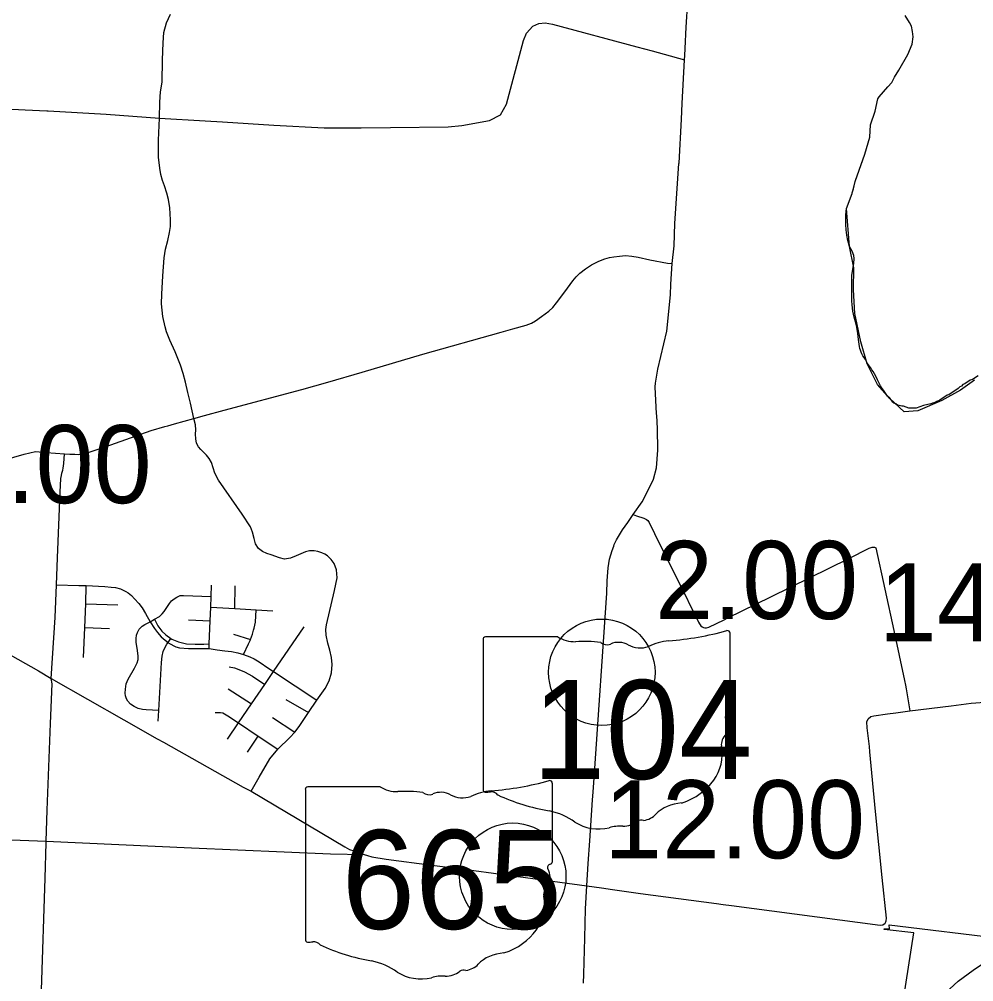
# Model space of a CAD drawing. Extents: x 1659811 to 1934326, y 644115 to 934867.
# Drawn here: x 1810912 to 1824362, y 663921 to 677476 of the extents above; entities that cross this region are included whole.
import ezdxf

# ---------------------------------------------------------------- set-up
doc = ezdxf.new("R2010")
doc.units = 0
for name, color, linetype in [('Default', 7, 'Continuous'), ('GM_X_City_Street', 7, 'Continuous'), ('GM_X_Corporation', 7, 'Continuous'), ('GM_X_County_Road', 7, 'Continuous'), ('GM_X_State_Route', 7, 'Continuous'), ('GM_X_State_Shield', 7, 'Continuous'), ('GM_X_Township', 7, 'Continuous'), ('GM_X_Township_Road', 7, 'Continuous')]:
    doc.layers.add(name, color=color, linetype=linetype)

msp = doc.modelspace()

# ---------------------------------------------------------------- linework, layer by layer
at = {"layer": 'Default'}
for centre in [(1819121, 668279), (1817866, 665407)]:
    msp.add_circle(centre, 750, dxfattribs=at)
at = {"layer": 'GM_X_City_Street'}
for points in [[(1813371, 671853), (1813325, 672068), (1813288, 672219), (1813255, 672367), (1813224, 672487), (1813186, 672606), (1813109, 672790), (1813036, 672955), (1812989, 673072), (1812967, 673143), (1812934, 673292), (1812918, 673466), (1812919, 673605), (1812936, 673864), (1812955, 674114), (1812972, 674238), (1813004, 674362), (1813030, 674473), (1813041, 674557), (1813043, 674649), (1813032, 674821), (1813016, 674937), (1812991, 675029), (1812959, 675131), (1812930, 675207), (1812908, 675291), (1812891, 675379), (1812874, 675536), (1812874, 675771), (1812889, 676084), (1812895, 676306), (1812902, 676452), (1812924, 676588), (1812932, 676903), (1812940, 677144), (1812948, 677290), (1812987, 677426), (1813041, 677549)], [(1819830, 677029), (1820001, 676982), (1820288, 676905)], [(1810161, 676241), (1810328, 676234), (1810996, 676200), (1811302, 676188), (1811320, 676187)], [(1811320, 676187), (1812139, 676140), (1812889, 676084), (1813531, 676044)], [(1812964, 671740), (1813007, 671752), (1813102, 671780), (1813371, 671853)], [(1813371, 671853), (1813524, 671895)], [(1814180, 666603), (1814291, 666801), (1814442, 667062), (1814554, 667195), (1814727, 667360), (1814796, 667438), (1814856, 667514), (1814989, 667712), (1815107, 667885), (1815223, 668049), (1815281, 668158), (1815311, 668272), (1815321, 668387), (1815311, 668487), (1815289, 668592), (1815259, 668688), (1815237, 668800), (1815234, 668881), (1815241, 668947), (1815354, 669430), (1815390, 669609), (1815383, 669721), (1815349, 669811), (1815305, 669869), (1815256, 669921), (1815219, 669941), (1815178, 669963), (1815121, 669980), (1815066, 669988), (1815004, 669988), (1814945, 669974), (1814816, 669918), (1814732, 669884), (1814651, 669874), (1814577, 669890), (1814463, 669931), (1814403, 669953), (1814338, 669980), (1814285, 670023), (1814242, 670088), (1814220, 670164), (1814197, 670252), (1814172, 670328), (1814054, 670505), (1813719, 670987), (1813666, 671083), (1813620, 671234), (1813586, 671292), (1813549, 671336), (1813470, 671416), (1813437, 671455), (1813409, 671506), (1813398, 671565), (1813394, 671634), (1813398, 671695), (1813394, 671765), (1813371, 671853)], [(1810689, 671267), (1810983, 671351), (1811142, 671387), (1811295, 671373), (1811548, 671356)], [(1811438, 669509), (1811752, 669502)], [(1811752, 669502), (1811856, 669500), (1812119, 669485), (1812205, 669479), (1812270, 669471), (1812338, 669454), (1812414, 669418), (1812445, 669399), (1812492, 669359), (1812538, 669315), (1812595, 669248), (1812644, 669186), (1812693, 669108), (1812757, 668992), (1812820, 668894), (1812861, 668838), (1812911, 668777), (1812969, 668731), (1813010, 668700), (1813021, 668691), (1813117, 668638), (1813169, 668624), (1813298, 668612), (1813586, 668612), (1813700, 668595), (1813807, 668582), (1813905, 668570), (1813994, 668554), (1814072, 668528), (1814161, 668495), (1814222, 668470), (1814293, 668425), (1814427, 668331), (1814493, 668288), (1815107, 667885)], [(1811816, 668488), (1811834, 668910), (1811848, 669242), (1811856, 669500)], [(1813586, 668612), (1813589, 668680), (1813602, 669006), (1813610, 669198), (1813616, 669346), (1813623, 669508)], [(1813949, 669178), (1813954, 669498)], [(1812757, 668992), (1812816, 669026), (1812887, 669067), (1812927, 669104), (1812956, 669136), (1813031, 669249), (1813059, 669284), (1813094, 669315), (1813133, 669339), (1813180, 669361), (1813226, 669361), (1813616, 669346)], [(1811848, 669242), (1812300, 669229)], [(1813610, 669198), (1813949, 669178), (1814252, 669159), (1814484, 669145)], [(1814072, 668528), (1814142, 668682), (1814165, 668727), (1814171, 668743), (1814197, 668816), (1814212, 668872), (1814221, 668901), (1814239, 668985), (1814252, 669159)], [(1812877, 667743), (1812699, 667748), (1812649, 667754), (1812586, 667771), (1812533, 667796), (1812482, 667830), (1812444, 667872), (1812423, 667905), (1812409, 667947), (1812405, 667985), (1812407, 668042), (1812420, 668117), (1812449, 668184), (1812536, 668335), (1812575, 668413), (1812589, 668459), (1812587, 668511), (1812572, 668620), (1812559, 668698), (1812558, 668757), (1812564, 668800), (1812579, 668840), (1812603, 668885), (1812643, 668927), (1812680, 668954), (1812757, 668992)], [(1812816, 669026), (1812866, 668932), (1812922, 668857), (1812978, 668807), (1813049, 668755), (1813064, 668745), (1813154, 668709), (1813269, 668682), (1813389, 668673), (1813511, 668677), (1813589, 668680)], [(1813298, 669019), (1813602, 669006)], [(1811834, 668910), (1812186, 668895)], [(1813931, 668818), (1814171, 668743)], [(1814493, 668288), (1814928, 668921)], [(1812868, 667589), (1812877, 667743), (1812917, 668416), (1812927, 668506), (1812942, 668574), (1812967, 668631), (1812993, 668676), (1813010, 668700), (1813049, 668755)], [(1813846, 667336), (1814002, 667566), (1814186, 667836), (1814371, 668107), (1814493, 668288)], [(1813871, 668355), (1813943, 668342), (1814004, 668319), (1814086, 668284), (1814200, 668225), (1814371, 668107)], [(1813858, 668045), (1814186, 667836)], [(1823399, 668099), (1823408, 668048), (1823461, 667737)], [(1814668, 667896), (1814989, 667712)], [(1813672, 667714), (1813716, 667712), (1813746, 667711), (1813781, 667706), (1813852, 667667), (1814002, 667566), (1814278, 667381), (1814554, 667195)], [(1814481, 667641), (1814796, 667438)], [(1814126, 667154), (1814278, 667381)]]:
    msp.add_lwpolyline(points, dxfattribs=at)
at = {"layer": 'GM_X_Corporation'}
for points in [[(1824422, 672453), (1824345, 672402), (1824311, 672393), (1824234, 672342), (1824209, 672333), (1824191, 672308), (1824166, 672299), (1824140, 672274), (1824012, 672188), (1823987, 672180), (1823884, 672112), (1823842, 672095), (1823816, 672078), (1823782, 672069), (1823757, 672060), (1823654, 672035), (1823552, 672001), (1823449, 672001), (1823373, 672026), (1823347, 672026), (1823313, 672035), (1823287, 672043), (1823262, 672060), (1823236, 672069), (1823212, 672089), (1823197, 672115), (1823177, 672141), (1823148, 672170), (1823107, 672222), (1823090, 672252), (1823070, 672278), (1823046, 672313), (1823032, 672342), (1823020, 672368), (1823006, 672400), (1822991, 672429), (1822962, 672481), (1822945, 672513), (1822927, 672539), (1822907, 672571), (1822866, 672629), (1822852, 672658), (1822837, 672685), (1822817, 672711), (1822799, 672737), (1822785, 672763), (1822773, 672789), (1822767, 672815), (1822756, 672841), (1822751, 672869), (1822743, 672935), (1822734, 673004), (1822726, 673056), (1822719, 673105), (1822708, 673162), (1822694, 673214), (1822676, 673282), (1822660, 673367), (1822650, 673455), (1822646, 673511), (1822644, 673569), (1822643, 673637), (1822645, 673698), (1822645, 673747), (1822645, 673805), (1822646, 673867), (1822651, 673929), (1822661, 673984), (1822671, 674038), (1822675, 674106), (1822671, 674150), (1822649, 674212), (1822613, 674277), (1822586, 674362), (1822574, 674436), (1822566, 674509), (1822560, 674586), (1822558, 674651), (1822561, 674723), (1822569, 674813), (1822647, 675022), (1822650, 675033), (1822665, 675087), (1822691, 675193), (1822694, 675207), (1822828, 675577), (1822851, 675655), (1822897, 675813), (1822908, 675991), (1822974, 676180), (1823012, 676355), (1823028, 676384), (1823152, 676525), (1823208, 676586), (1823247, 676661), (1823305, 676759), (1823431, 676978), (1823492, 677123), (1823510, 677230), (1823498, 677303), (1823485, 677377), (1823457, 677430), (1823394, 677531)], [(1823332, 663432), (1823518, 664608), (1823100, 664659), (1823103, 664672), (1823175, 664665), (1823170, 664722), (1824798, 664523)]]:
    msp.add_lwpolyline(points, dxfattribs=at)
at = {"layer": 'GM_X_County_Road'}
msp.add_lwpolyline([(1813531, 676044), (1813778, 676029), (1814498, 675982), (1815209, 675949), (1815732, 675949), (1816142, 675951), (1816958, 675960), (1817150, 675979), (1817539, 676052), (1817692, 676132), (1817778, 676281), (1818016, 677175), (1818058, 677282), (1818149, 677378), (1818232, 677416), (1818323, 677425), (1818424, 677407), (1819616, 677087), (1819830, 677029)], dxfattribs=at)
at = {"layer": 'GM_X_State_Route'}
for points in [[(1820296, 677064), (1820311, 677364), (1820331, 677730), (1820345, 677961), (1820346, 677975), (1820365, 678298), (1820393, 678749), (1820402, 679022)], [(1820288, 676905), (1820291, 676966), (1820296, 677064)], [(1820208, 675444), (1820209, 675449), (1820243, 676069), (1820255, 676288), (1820288, 676905)], [(1819894, 671894), (1819893, 671920), (1819872, 672301), (1819877, 672349), (1819912, 672547), (1820038, 673084), (1820088, 673593), (1820092, 673746), (1820110, 674036), (1820141, 674286), (1820149, 674599), (1820208, 675444)], [(1819288, 670053), (1819297, 670077), (1819327, 670145), (1819411, 670285), (1819487, 670390), (1819563, 670503), (1819691, 670679), (1819757, 670808), (1819851, 671000), (1819892, 671158), (1819910, 671407), (1819904, 671713), (1819894, 671894)], [(1808076, 670072), (1808114, 670051), (1808982, 669552), (1810244, 668838), (1810520, 668670), (1811183, 668298), (1811362, 668191), (1812385, 667611), (1812857, 667344)], [(1819017, 666852), (1819017, 666860), (1819192, 669395), (1819197, 669568), (1819211, 669750), (1819230, 669872), (1819266, 669993), (1819288, 670053)], [(1822891, 667232), (1822862, 667499), (1822856, 667582), (1822875, 667625), (1822910, 667656), (1822955, 667668), (1823148, 667696), (1823266, 667709), (1823461, 667737), (1824045, 667809), (1824325, 667846), (1824516, 667859), (1824733, 667846)], [(1812857, 667344), (1812945, 667295)], [(1812945, 667295), (1814068, 666660), (1814180, 666603), (1815498, 665821), (1815564, 665785), (1815626, 665766), (1815698, 665736), (1815770, 665711), (1815820, 665697), (1815821, 665697)], [(1820946, 664994), (1823042, 664717), (1823082, 664723), (1823115, 664746), (1823124, 664764), (1823128, 664780), (1823130, 664816), (1823073, 665389), (1822978, 666317), (1822899, 667159), (1822891, 667232)], [(1818999, 666589), (1818999, 666596), (1819017, 666852)], [(1818991, 666483), (1818999, 666589)], [(1818951, 665904), (1818991, 666483)], [(1818929, 665588), (1818951, 665904)], [(1815821, 665697), (1815880, 665680), (1816082, 665646), (1816726, 665563), (1817285, 665493)], [(1818908, 665272), (1818929, 665588)], [(1817285, 665493), (1817287, 665493), (1817319, 665489), (1818151, 665376), (1818908, 665272)], [(1818882, 664535), (1818893, 664950), (1818908, 665272)], [(1818908, 665272), (1819117, 665243)], [(1819117, 665243), (1819273, 665220)], [(1819273, 665220), (1819666, 665165), (1820737, 665022)], [(1820737, 665022), (1820831, 665009), (1820946, 664994)], [(1818865, 663903), (1818869, 664029), (1818882, 664535)]]:
    msp.add_lwpolyline(points, dxfattribs=at)
at = {"layer": 'GM_X_State_Shield'}
for p, q in [((1820928, 667725), (1820928, 668830)), ((1817447, 668741), (1817447, 666628)), ((1818501, 668778), (1817481, 668778)), ((1820927, 667725), (1820928, 667725)), ((1815997, 666666), (1814978, 666666)), ((1818424, 665613), (1818424, 666718)), ((1814944, 666629), (1814944, 664516)), ((1818424, 665613), (1818424, 665613))]:
    msp.add_line(p, q, dxfattribs=at)
for centre, major_axis, start_param, end_param in [((1819688, 671659), (3691, 0), 4.814394, 5.042369), ((1820889, 668835), (38.7, 0), 6.141152, 7.989035), ((1817487, 668746), (40.3, 0), 1.712693, 3.28349), ((1818743, 669023), (391, 0), 4.042523, 4.731795), ((1818873, 667591), (1404, 0), 1.404758, 1.657858), ((1819192, 668757), (113, 0), 3.836095, 5.185415), ((1819357, 668513), (235, 0), 0.950623, 2.079405), ((1820159, 668132), (743, 0), 1.699011, 2.107814), ((1819660, 668848), (282, 0), 4.081561, 5.145723), ((1820886, 667720), (41.5, 0), 5.05454, 6.418171), ((1820919, 667644), (60, 0), 1.883978, 3.671073), ((1820537, 667504), (360, 0), 5.934695, 6.695948), ((1821066, 667262), (262, 0), 2.387724, 3.262537), ((1819894, 667121), (923, 0), 5.101752, 6.440018), ((1814983, 666634), (40.3, 0), 1.712693, 3.28349), ((1816240, 666911), (391, 0), 4.042523, 4.731795), ((1817184, 669547), (3691, 0), 4.814394, 5.042369), ((1818385, 666723), (38.7, 0), 6.141152, 7.989035), ((1816369, 665479), (1404, 0), 1.404758, 1.657858), ((1816688, 666645), (113, 0), 3.836095, 5.185415), ((1816854, 666401), (235, 0), 0.950623, 2.079405), ((1817157, 666736), (282, 0), 4.081561, 5.145723), ((1817655, 666020), (743, 0), 1.699011, 2.107814), ((1817487, 666624), (40.7, 0), 3.00124, 4.508301), ((1817494, 666840), (310, 0), 4.665946, 4.897461), ((1817557, 666506), (112, 0), 0.519207, 1.627899), ((1818970, 668405), (2665, 0), 4.195997, 4.488961), ((1820284, 666035), (506, 0), 1.647645, 2.488434), ((1818176, 665679), (834, 0), 0.823519, 1.323587), ((1819643, 666423), (298, 0), 4.937069, 5.64225), ((1819078, 666496), (529, 0), 4.026481, 4.996735), ((1819383, 665765), (435, 0), 1.495662, 1.94098), ((1819422, 666338), (282, 0), 4.691044, 5.507374), ((1819677, 666133), (79.4, 0), 1.147584, 2.315152), ((1818415, 665532), (60, 0), 1.883978, 3.671073), ((1818383, 665608), (41.5, 0), 5.05454, 6.418171), ((1818033, 665392), (360, 0), 5.934695, 6.695948), ((1818563, 665150), (262, 0), 2.387724, 3.262537), ((1817391, 665009), (923, 0), 5.101752, 6.440018), ((1814984, 664512), (40.7, 0), 3.00124, 4.508301), ((1814990, 664728), (310, 0), 4.665946, 4.897461), ((1815053, 664394), (112, 0), 0.519207, 1.627899), ((1816467, 666293), (2665, 0), 4.195997, 4.488961), ((1815672, 663567), (834, 0), 0.823519, 1.323587), ((1817780, 663923), (506, 0), 1.647645, 2.488434), ((1816918, 664226), (282, 0), 4.691044, 5.507374), ((1817173, 664021), (79.4, 0), 1.147584, 2.315152), ((1817140, 664311), (298, 0), 4.937069, 5.64225), ((1816574, 664384), (529, 0), 4.026481, 4.996735), ((1816880, 663653), (435, 0), 1.495662, 1.94098)]:
    msp.add_ellipse(centre, major_axis=major_axis, ratio=0.8, start_param=start_param, end_param=end_param, dxfattribs=at)
at = {"layer": 'GM_X_Township'}
for points in [[(1824371, 672393), (1824176, 672251), (1823910, 672109), (1823572, 671961), (1823379, 671945), (1823178, 672135), (1823007, 672332), (1822861, 672623), (1822770, 672933), (1822688, 673332), (1822668, 673666), (1822672, 673975), (1822611, 674274), (1822569, 674813), (1822647, 675022), (1822691, 675193), (1822828, 675577), (1822897, 675813), (1822908, 675991), (1822974, 676180), (1823012, 676355), (1823028, 676384), (1823152, 676525), (1823208, 676586), (1823247, 676661), (1823305, 676759), (1823431, 676978), (1823492, 677123), (1823510, 677230), (1823498, 677303), (1823485, 677377), (1823457, 677430), (1823394, 677531)], [(1823965, 663763), (1824144, 663928), (1824354, 664086), (1824570, 664230)]]:
    msp.add_lwpolyline(points, dxfattribs=at)
at = {"layer": 'GM_X_Township_Road'}
for points in [[(1818639, 673691), (1818713, 673791), (1818758, 673849), (1818811, 673898), (1818889, 673962), (1818974, 674019), (1819078, 674068), (1819165, 674100), (1819229, 674119), (1819292, 674130), (1819370, 674141), (1819453, 674147), (1819543, 674139), (1819631, 674125), (1819799, 674090), (1820046, 674039), (1820110, 674036)], [(1815261, 672367), (1815745, 672507), (1816597, 672757), (1817701, 673069), (1817865, 673116), (1818057, 673170), (1818129, 673198), (1818188, 673231), (1818270, 673290), (1818376, 673366), (1818429, 673417), (1818483, 673483), (1818628, 673677), (1818639, 673691)], [(1813524, 671895), (1813800, 671971), (1814892, 672260), (1815261, 672367)], [(1811548, 671356), (1811623, 671352), (1811696, 671349), (1811744, 671348), (1811771, 671349), (1811803, 671353), (1811838, 671360), (1811871, 671368), (1812121, 671456), (1812771, 671685), (1812964, 671740)], [(1811362, 668191), (1811416, 669051), (1811438, 669509), (1811451, 669891), (1811487, 670815), (1811500, 671008), (1811506, 671050), (1811514, 671082), (1811527, 671127), (1811533, 671154), (1811541, 671218), (1811548, 671356)], [(1819563, 670503), (1819609, 670483), (1819712, 670450), (1819750, 670431), (1819767, 670418), (1819780, 670405), (1819790, 670390), (1819937, 670080), (1820189, 669584), (1820484, 668987), (1820497, 668962), (1820515, 668934), (1820533, 668920), (1820552, 668909), (1820571, 668904), (1820596, 668904), (1820630, 668914), (1820845, 669019), (1820895, 669044)], [(1820895, 669044), (1821502, 669344), (1822601, 669882), (1822886, 670029), (1822929, 670042), (1822961, 670042), (1822980, 670030), (1823235, 668867), (1823388, 668165), (1823399, 668099)], [(1811291, 665875), (1811292, 665901), (1811306, 666338), (1811353, 667557), (1811374, 668115), (1811362, 668191)], [(1807386, 666038), (1809447, 665969), (1811292, 665901), (1813340, 665809), (1815297, 665721), (1815770, 665711)], [(1811039, 658133), (1811072, 659073), (1811090, 659728), (1811110, 660352), (1811119, 660831), (1811186, 662602), (1811227, 663802), (1811276, 665382), (1811291, 665875)]]:
    msp.add_lwpolyline(points, dxfattribs=at)

# ---------------------------------------------------------------- texts
at = {"layer": 'Default'}
for s, p in [('10.00', (1809097, 670661)), ('2.00', (1819871, 669029)), ('14.00', (1823024, 668713)), ('12.00', (1819150, 665659))]:
    msp.add_text(s, height=1100, dxfattribs=at).set_placement(p)
at = {"layer": 'GM_X_State_Shield'}
for s, p in [('104', (1818139, 666777)), ('665', (1815454, 664665))]:
    msp.add_text(s, height=1392.2, dxfattribs=at).set_placement(p)

doc.saveas('drawing.dxf')
